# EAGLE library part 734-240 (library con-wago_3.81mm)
Serie 734, Stiftleiste (für Leiterplatten) Einlötstift gerade 1 x 1 mm / Series 734, Male header (for PCBs) Straight solder pin 1 x 1 mm Polzahl / Pole No.: 10 Rastermaß / Pitch: 3.81 mm Bemessungsspannung / Rated Voltage: 160 V Nennstrom / Nominal Current: 10 A Lötstiftlänge: / Solder Pin Length: 4.5 mm Farbe / Color: orange / orange Stand: 01.01.2012. Die jeweils aktuellen Daten zu diesem Artikel finden Sie in unserem Produktkatalog, den Sie unter www.wago.com einsehen können. As of: 01/01/2012. Please find the newest data for this article in our product catalogue, which can be viewed under www.wago.com.
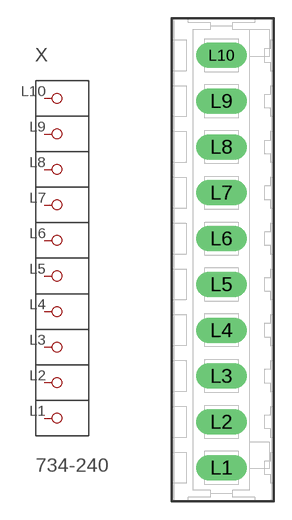
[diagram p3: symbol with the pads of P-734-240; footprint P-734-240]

Designator prefix X

## 734-240  [P-734-240]
L1  P1.1
L2  P2
L3  P3
L4  P4
L5  P5
L6  P6
L7  P7
L8  P8
L9  P9
L10  P10

## Footprint P-734-240 (pad centres in mm)
drill 1.4 long: L1 -0.1,-17.295; L2 -0.1,-13.485; L3 -0.1,-9.675; L4 -0.1,-5.865; L5 -0.1,-2.055; L6 -0.1,1.755; L7 -0.1,5.565; L8 -0.1,9.375; L9 -0.1,13.185; L10 -0.1,16.995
